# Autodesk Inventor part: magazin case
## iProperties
Created: 2006-04
Part Number: magazin case
Document SubType Name: Modeling
Designer: Калинин
Author: Калинин
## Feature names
1. Выдавливание1 [Extrusion]
2. Выдавливание2 [Extrusion]
3. Выдавливание3 [Extrusion]
4. Выдавливание4 [Extrusion]
5. Выдавливание12 [Extrusion]
6. Выдавливание13 [Extrusion]
7. Выдавливание14 [Extrusion]
8. Разделение1
9. Сопряжение1 [Fillet]
10. Сопряжение2 [Fillet]
11. Выдавливание15 [Extrusion]
12. Выдавливание16 [Extrusion]
13. Разделение2
14. Разделение3
15. Выдавливание17 [Extrusion]
16. Выдавливание18 [Extrusion]
17. Выдавливание19 [Extrusion]
18. Выдавливание20 [Extrusion]
19. Выдавливание21 [Extrusion]
20. Выдавливание22 [Extrusion]
21. Сопряжение3 [Fillet]
22. Сопряжение4 [Fillet]
23. Сопряжение5 [Fillet]
24. Сопряжение7 [Fillet]
25. Выдавливание24 [Extrusion]
26. Разделение4
27. Выдавливание31 [Extrusion]
28. Выдавливание32 [Extrusion]
29. Разделение5
30. Разделение6
31. Выдавливание33 [Extrusion]
32. Сопряжение10 [Fillet]
33. Сопряжение11 [Fillet]
34. Сопряжение12 [Fillet]
35. Вращение2 [Revolution]
36. Выдавливание34 [Extrusion]
37. Вращение3 [Revolution]
38. Выдавливание35 [Extrusion]
39. Выдавливание36 [Extrusion]
40. Выдавливание37 [Extrusion]
41. Выдавливание38 [Extrusion]
42. Выдавливание39 [Extrusion]
43. Вращение4 [Revolution]
44. Сопряжение13 [Fillet]
45. Сопряжение14 [Fillet]
46. Сопряжение15 [Fillet]
47. Выдавливание40 [Extrusion]
48. Выдавливание41 [Extrusion]
49. Сопряжение16 [Fillet]
50. Сопряжение17 [Fillet]
51. Выдавливание42 [Extrusion]
52. Сопряжение18 [Fillet]
53. Сопряжение19 [Fillet]
54. Сопряжение20 [Fillet]
55. Сопряжение21 [Fillet]
56. Сопряжение22 [Fillet]
57. Сопряжение23 [Fillet]
58. Сопряжение24 [Fillet]
